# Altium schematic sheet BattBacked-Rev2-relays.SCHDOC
size Tabloid; Organization: Monterey Bay Aquarium Research Institute; Address1: 7700 Sandholdt Rd; Address2: Moss Landing, CA 95039-9644; CompanyName: MBARI
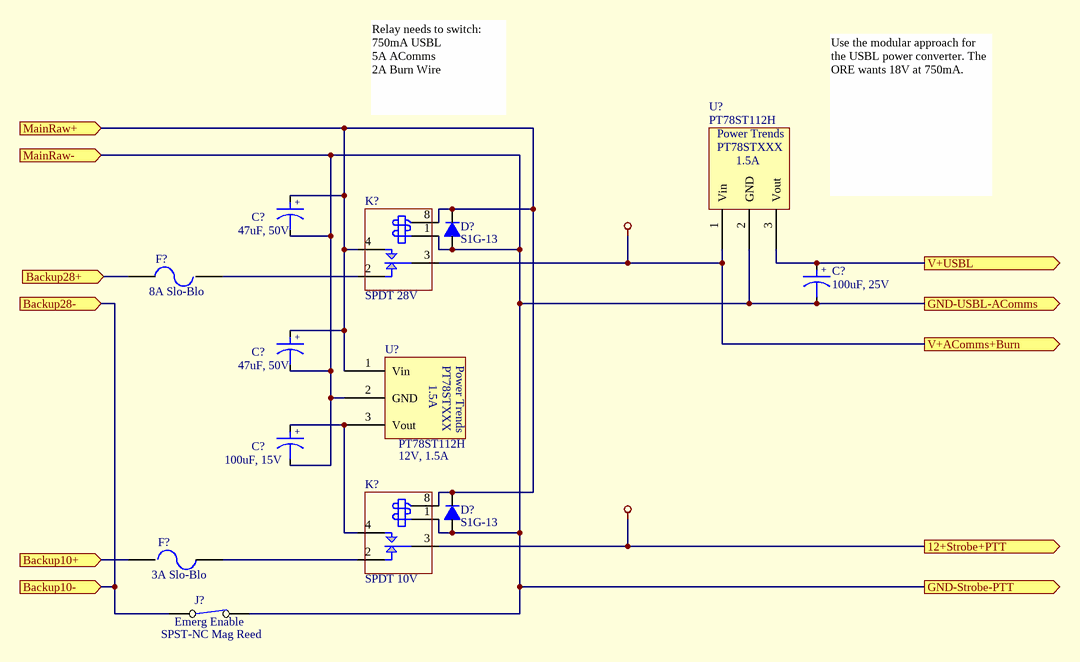
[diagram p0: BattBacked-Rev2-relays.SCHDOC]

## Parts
(Parts that share a designator on the sheet are numbered #1, #2 ... from top to bottom, then left to right.)
C?#1  47uF, 50V
C?#2  100uF, 25V
C?#3  47uF, 50V
C?#4  100uF, 15V
D?#1  S1G-13  [SMA]
D?#2  S1G-13  [SMA]
F?#1  8A Slo-Blo  [PIN-W2/E2.8]
F?#2  3A Slo-Blo  [PIN-W2/E2.8]
J?  Emerg Enable  DescSheet: SPST-NC Mag Reed  [CGRID2]
K?#1  SPDT 28V  [NAIS-LZ]
K?#2  SPDT 10V  [NAIS-LZ]
U?#1  PT78ST112H  [PT78ST-HORIZ]
U?#2  PT78ST112H  DescSheet: 12V, 1.5A  [PT78ST-HORIZ]

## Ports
12+Strobe+PTT (out), Backup10+ (in), Backup10- (in), Backup28+ (in), Backup28- (in), GND-Strobe-PTT (out), GND-USBL-AComms (out), MainRaw+ (in), MainRaw- (in), V+AComms+Burn (out), V+USBL (out)

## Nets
10VDC: K?#2.3(COMMON) ; port 12+Strobe+PTT
28VDC: K?#1.3(COMMON) U?#1.1(Vin) ; port V+AComms+Burn
Backup10+: F?#2.1 ; port Backup10+
Backup10-: J?.1(COMMON) ; port Backup28-, port Backup10-
Backup28+: F?#1.1 ; port Backup28+
GND-Strobe-PTT: C?#1.2 C?#2.2 C?#3.2 C?#4.2 D?#1.1(K) D?#2.1(K) J?.2(NO) K?#1.1(COIL+) K?#2.1(COIL+) U?#1.2(GND) U?#2.2(GND) ; port MainRaw-, port GND-USBL-AComms, port GND-Strobe-PTT
MainRaw+: C?#1.1 C?#3.1 D?#1.2(A) D?#2.2(A) K?#1.4(NO) K?#1.8(COIL-) K?#2.8(COIL-) U?#2.1(Vin) ; port MainRaw+
V+USBL: C?#2.1 U?#1.3(Vout) ; port V+USBL
NetC?#4_1: C?#4.1 K?#2.4(NO) U?#2.3(Vout)
NetF?#1_2: F?#1.2 K?#1.2(NC)
NetF?#2_2: F?#2.2 K?#2.2(NC)

Not connected (* = marked no-connect by the designer): K?#1 5(NO) 6(COMMON) 7(NC); K?#2 5(NO) 6(COMMON) 7(NC)

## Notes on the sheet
- Relay needs to switch:
  750mA USBL
  5A AComms
  2A Burn Wire
- Use the modular approach for the USBL power converter. The ORE wants 18V at 750mA.

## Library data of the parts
C?#1-C?#4 = CAPACITOR POL: Capacitor
D?#1 D?#2 = DIODE_S: Diode; Manufacturer: Diodes Inc; VendorPartNo: S1GDICT-ND; Cost/ea: 0.288; DescSheet: 1A, 400V; Reference: T033, 578; Vendor: Digi-Key
F?#1 F?#2 = Fuse 2: Fuse; Manufacturer: Generic Components
J? = SW-SPST-NC
K?#1 K?#2 = RELAY-NAIS-LZ-SPDT: Nais LZ Relay SPDT; ManufPartNo: ALZ12F24; VendorPartNo: 255-1447-ND; Cost/ea: 2.16; Reference: T033, 942; Vendor: Digi-Key
U?#1 U?#2 = PT78STXXX: Power Trends Switching Reg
